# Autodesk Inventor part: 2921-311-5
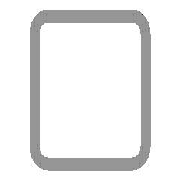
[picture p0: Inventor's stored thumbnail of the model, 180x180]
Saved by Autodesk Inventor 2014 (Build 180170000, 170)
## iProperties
IsCustomPart: 1
Company: NHTSA/VRTC
Created: 2012-02
Part Number: 2921-311-5
Material: Steel, Mild
Description: BENCH FRAME TUBE #5
Document SubType Name: Modeling
Standard: AISC
Designer: Dave Walker
Standards Organization: ANSI
Language: en-US
Size Designation: 1-1/2x1-1/2x1/8 - 20.63
Categories: <MemberInstance><Categories><Category DisplayName="Structural Shapes" InternalName="089c4875-fa83-4c05-b084-43b9cc11f5ed" Mnemonic="GRDR"><CategoryParameter Dis
Stock Number: T.S. 1 1/2 x 1 1/2 x 1/8 x 524.0mm (20.63")
Density: 1 g/cm^3
Project: CHILD SIDE IMPACT SLED
Appearance: Steel
G_L: 20.630 in
Author: Dave Walker
Title: 2921-200-5
Subject: Child Side Impact Sled
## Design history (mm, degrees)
node "Start plane"
node "End plane"
sketch "Sketch"
  geometry: L1 (-19.05, -12.7)-(-19.05, 12.7); L2 (-12.7, 19.05)-(12.7, 19.05); L3 (19.05, 12.7)-(19.05, -12.7); L4 (12.7, -19.05)-(-12.7, -19.05); L5 (-12.7, 15.875)-(12.7, 15.875); L6 (15.875, 12.7)-(15.875, -12.7); L7 (12.7, -15.875)-(-12.7, -15.875); L8 (-15.875, -12.7)-(-15.875, 12.7); L9 (0, 28.511)-(0, -28.511) reference; L10 (-28.511, 0)-(28.511, 0) reference; A1 r 6.35 centre (-12.7, -12.7) between (-19.05, -12.7) and (-12.7, -19.05); A2 r 6.35 centre (-12.7, 12.7) between (-12.7, 19.05) and (-19.05, 12.7); A3 r 6.35 centre (12.7, 12.7) between (19.05, 12.7) and (12.7, 19.05); A4 r 6.35 centre (12.7, -12.7) between (12.7, -19.05) and (19.05, -12.7); A5 r 3.175 centre (-12.7, 12.7) between (-12.7, 15.875) and (-15.875, 12.7); A6 r 3.175 centre (12.7, 12.7) between (15.875, 12.7) and (12.7, 15.875); A7 r 3.175 centre (12.7, -12.7) between (12.7, -15.875) and (15.875, -12.7); A8 r 3.175 centre (-12.7, -12.7) between (-15.875, -12.7) and (-12.7, -15.875)
  constraints: 16 end point, 16 point on circle, 8 centre point, 8 tangent, 4 parallel, 3 equal radius, 2 perpendicular, 7 other
  dimensions: "d10" = 38.1 distance between parallel lines of L2 L4 (= G_H); "d11" = 38.1 distance between parallel lines of L1 L3 (= G_W); "d12" = 3.175 distance between parallel lines of L3 L6 (= G_T); "d15" = 19.05 distance between parallel lines of L2 L10 (= 0.5 x d10); "d16" = 19.05 distance between parallel lines of L9 L3 (= 0.5 x d11); "d17" = 6.35 radius of A1 (= G_IR)
extrude "Body" new body sketch "Sketch" stored distance "d3" = 524.002 (= G_L); taper "d4" = 0 deg
node "Driven Length"
  sketch "Sketch3"
    geometry: L1 (0, 0)-(10, 0) reference
    constraints: 2 end point, 1 horizontal
  workplane "Work Plane3"
  sketch "Sketch4"
    geometry: L1 (-2, 0)-(12, 0) reference; L2 (-2, 524.002)-(12, 524.002) reference
    dimensions: "d19" = 524.002 distance between parallel lines of L1 L2 (derived)
sketch "Sketch5"
  geometry: L1 (524.002, -6.35)-(0, -6.35) reference; L2 (524.002, 31.75)-(0, 31.75) reference; L3 (0, -6.35)-(6.718, 31.75); L4 (6.718, 31.75)-(0, 31.75); L5 (0, 31.75)-(0, -6.35); 1 further point
  constraints: 6 end point, 1 collinear, 1 perpendicular, 1 point on line
  dimensions: "d20" = 80 deg angle of L1 L3
extrude "Extrusion2" cut sketch "Sketch5" stored distance "d21" = 25.4; taper "d22" = 0 deg
sketch "Sketch6"
  geometry: L1 (25.4, 0)-(0, 0) reference; C1 r 3.569 at (12.7, 52.8) reference; C2 r 3.569 at (12.7, 258.8) reference; C3 r 3.569 at (12.7, 489.4) reference; 8 further points
  constraints: 4 midpoint, 3 coincident
hole "Hole1" sketch "Sketch6" at (12.7, 52.8), (12.7, 258.8), (12.7, 489.4) diameter "d27" = 4.9784; stored, may be unused: countersink angle "d31" = 82 deg, drill point angle "d33" = 118 deg; dims "d28" = 19.05, "d29" = 9.525, "d30" = 6.35, "d32" = 3.175
body "Solid1"
node "Reference1"
node "Reference2"
node "Reference3"
other parameters: "G_W" = 38.1 [user parameter; used in 1 equation term], "G_H" = 38.1 [user parameter; used in 1 equation term], "G_T" = 3.175 [user parameter; used in 1 equation term], "G_IR" = 6.35 [user parameter; used in 1 equation term], "G_L" = 524.002 (= d19) [user parameter; used in 1 equation term], "G_OFFSET_START" = 0 [user parameter; used in 1 equation term], "G_OFFSET_END" = 0 [user parameter; used in 1 equation term], "d13" = 0 (computed from G_OFFSET_START), "d14" = 524.002 (= G_OFFSET_END + B_L), "B_L" = 524.002 [user parameter; used in 1 equation term], "d18" = 90 deg
